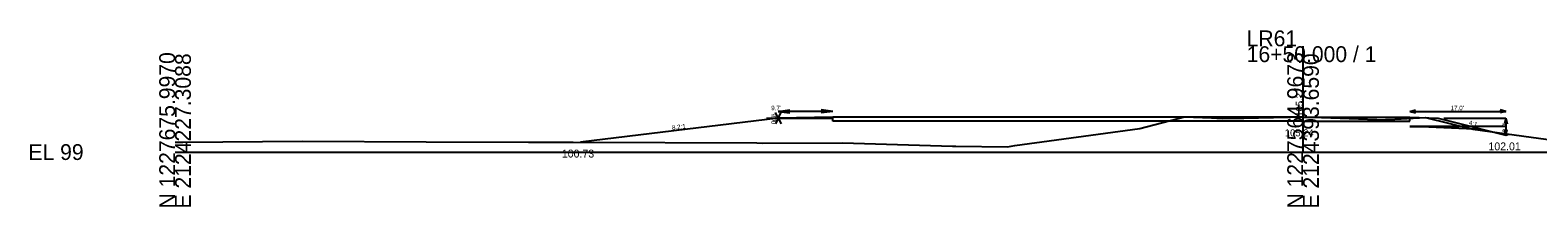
# Model space of a CAD drawing. Extents: x -26 to 1403, y -10 to 9574.
# Drawn here: x 974.3 to 1241.6, y 6490.3 to 6521.6 of the extents above; entities that cross this region are included whole.
import ezdxf

# ---------------------------------------------------------------- set-up
doc = ezdxf.new("R2010")
doc.units = 0
for name, color, linetype in [('XS_CELL', 7, 'Continuous'), ('XS_P_FINISHED_GRADE', 7, 'Continuous'), ('XS_P_FINISHED_GRADE_ELEV_TX', 7, 'Continuous'), ('XS_P_SUBGRADE_GRANULAR', 7, 'Continuous'), ('XS_P_SUBGRADE_PAVEMENT', 7, 'Continuous'), ('XS_P_TX_CLEARZONE', 7, 'Continuous'), ('XS_P_TX_DCH', 7, 'Continuous'), ('XS_P_TX_FS_BS', 7, 'Continuous'), ('XS_X_GROUND', 7, 'Continuous'), ('XS_X_GROUND_TX', 7, 'Continuous')]:
    doc.layers.add(name, color=color, linetype=linetype)

msp = doc.modelspace()

# ---------------------------------------------------------------- linework, layer by layer
at = {"layer": 'XS_CELL'}
for p, q in [((1200, 6500), (1200, 6518.74)), ((1000, 6500), (1200, 6500)), ((1200, 6500), (1400, 6500))]:
    msp.add_line(p, q, dxfattribs=at)
at = {"layer": 'XS_P_FINISHED_GRADE'}
for p, q in [((1106.95, 6506), (1071.88, 6501.73)), ((1116.62, 6506.21), (1106.95, 6506)), ((1200, 6506.21), (1116.62, 6506.21)), ((1200, 6506.21), (1218.93, 6506.21)), ((1218.93, 6506.21), (1223.94, 6506.01)), ((1223.94, 6506.01), (1235.94, 6503.01)), ((1235.94, 6503.01), (1236.45, 6503.18))]:
    msp.add_line(p, q, dxfattribs=at)
at = {"layer": 'XS_P_SUBGRADE_GRANULAR'}
for p, q in [((1106.53, 6506), (1116.62, 6506)), ((1116.62, 6506), (1114.62, 6506)), ((1236.14, 6504.51), (1218.93, 6504.51)), ((1218.93, 6504.51), (1220.93, 6504.51)), ((1220.93, 6504.51), (1231.65, 6504.08))]:
    msp.add_line(p, q, dxfattribs=at)
at = {"layer": 'XS_P_SUBGRADE_PAVEMENT'}
for p, q in [((1116.62, 6505.46), (1116.62, 6506.21)), ((1200, 6505.46), (1116.62, 6505.46)), ((1200, 6505.46), (1218.93, 6505.46)), ((1218.93, 6505.46), (1218.93, 6506.21))]:
    msp.add_line(p, q, dxfattribs=at)
at = {"layer": 'XS_P_TX_CLEARZONE'}
for p, q in [((1106.95, 6506), (1106.43, 6507)), ((1106.95, 6507.21), (1109, 6507.46)), ((1106.95, 6507.21), (1109, 6506.96)), ((1116.62, 6507.21), (1106.95, 6507.21)), ((1106.95, 6506), (1107.46, 6507)), ((1116.62, 6507.21), (1114.57, 6507.46)), ((1116.62, 6507.21), (1114.57, 6506.96)), ((1218.93, 6507.21), (1219.93, 6507.46)), ((1218.93, 6507.21), (1219.93, 6506.96)), ((1218.93, 6507.21), (1235.94, 6507.21)), ((1235.94, 6507.21), (1234.94, 6507.46)), ((1235.94, 6507.21), (1234.94, 6506.96)), ((1104.89, 6506), (1106.95, 6506)), ((1106.95, 6506), (1106.43, 6505)), ((1106.95, 6506), (1107.46, 6505)), ((1224.94, 6506.01), (1235.94, 6506.01)), ((1235.94, 6506.01), (1235.69, 6505.01)), ((1235.94, 6503.01), (1235.69, 6504.01)), ((1235.94, 6506.01), (1235.94, 6503.01)), ((1235.94, 6506.01), (1236.19, 6505.01)), ((1235.94, 6503.01), (1236.19, 6504.01))]:
    msp.add_line(p, q, dxfattribs=at)
at = {"layer": 'XS_X_GROUND'}
for p, q in [((1148.89, 6501.19), (1171.07, 6504.17)), ((1171.07, 6504.17), (1178.97, 6506.25)), ((1178.97, 6506.25), (1183.75, 6506.04)), ((1183.75, 6506.04), (1185.64, 6505.95)), ((1185.64, 6505.95), (1189.47, 6506.03)), ((1189.47, 6506.03), (1200.02, 6506.24)), ((1200.02, 6506.24), (1213.1, 6505.75)), ((1213.1, 6505.75), (1214.03, 6505.72)), ((1214.03, 6505.72), (1214.59, 6505.74)), ((1214.59, 6505.74), (1215.21, 6505.76)), ((1215.21, 6505.76), (1221.68, 6506.13)), ((1221.68, 6506.13), (1230.08, 6504.06)), ((1230.08, 6504.06), (1244.74, 6502.04)), ((1000, 6501.73), (1001.39, 6501.73)), ((1001.39, 6501.73), (1022.61, 6501.91)), ((1022.61, 6501.91), (1044.53, 6501.82)), ((1044.53, 6501.82), (1062.68, 6501.78)), ((1062.68, 6501.78), (1070.59, 6501.73)), ((1070.59, 6501.73), (1103.14, 6501.64)), ((1103.14, 6501.64), (1104.15, 6501.59)), ((1104.15, 6501.59), (1118.36, 6501.62)), ((1118.36, 6501.62), (1137.82, 6501.03)), ((1147.61, 6500.91), (1148.89, 6501.19)), ((1137.82, 6501.03), (1138.45, 6501.02)), ((1138.45, 6501.02), (1147.61, 6500.91))]:
    msp.add_line(p, q, dxfattribs=at)

# ---------------------------------------------------------------- texts
at = {"layer": 'XS_CELL'}
for s, p in [('LR61', (1190, 6518.74)), ('16+50.000 / 1', (1190, 6515.94)), ('EL 99', (974, 6498.6))]:
    msp.add_text(s, height=2.8, dxfattribs=at).set_placement(p)
for s, p in [('N 1227675.9970', (1000, 6490)), ('E 2124227.3088', (1002.8, 6490)), ('N 1227564.9673', (1200, 6490)), ('E 2124393.6590', (1202.8, 6490))]:
    msp.add_text(s, height=2.8, rotation=90, dxfattribs=at).set_placement(p)
at = {"layer": 'XS_P_FINISHED_GRADE_ELEV_TX'}
msp.add_text('105.21', height=1.25, rotation=90, dxfattribs=at).set_placement((1199.96, 6506.27))
at = {"layer": 'XS_P_TX_CLEARZONE'}
for s, p in [("0.0'", (1106.53, 6504.94)), ("3.0'", (1236.14, 6503.48))]:
    msp.add_text(s, height=0.8, rotation=90, dxfattribs=at).set_placement(p)
for s, p in [("9.7'", (1105.7, 6507.41)), ("17.0'", (1226.15, 6507.41))]:
    msp.add_text(s, height=0.8, dxfattribs=at).set_placement(p)
at = {"layer": 'XS_P_TX_DCH'}
for s, p in [('102.01', (1232.87, 6500.31)), ('100.73', (1068.58, 6499.03))]:
    msp.add_text(s, height=1.4, dxfattribs=at).set_placement(p)
at = {"layer": 'XS_P_TX_FS_BS'}
for s, rotation, p in [('1:0', 90, (1106.75, 6505.28)), ('8.2:1', 6.9458, (1088.15, 6503.91)), ('4:1', 345.9674, (1229.33, 6504.87))]:
    msp.add_text(s, height=0.8, rotation=rotation, dxfattribs=at).set_placement(p)
at = {"layer": 'XS_X_GROUND_TX'}
msp.add_text('105.24', height=1.25, rotation=360, dxfattribs=at).set_placement((1196.76, 6502.79))

doc.saveas('drawing.dxf')
